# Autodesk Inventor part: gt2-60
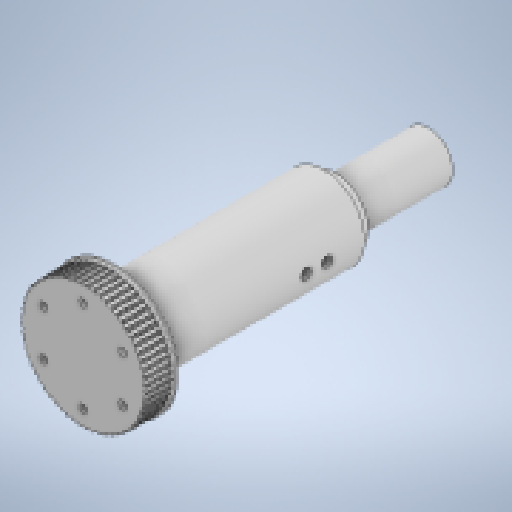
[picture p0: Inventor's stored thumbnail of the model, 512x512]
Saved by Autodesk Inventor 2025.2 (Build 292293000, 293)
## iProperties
Created: 2025-06
Part Number: gt2-60
Material: Generico
Document SubType Name: Modeling
Designer: Ryzen5700u
Density: 1 g/cm^3
Appearance: Default
Author: Ryzen5700u
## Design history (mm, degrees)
sketch "Schizzo1"
  geometry: C1 r 4.963 at (0, 0); A1 r 18.592 centre (0, 0) between (-0.5, -18.585) and (0.5, -18.585); A2 r 0.65 centre (0, -19) between (0.628, -18.833) and (0.5, -18.585); A3 r 0.2 centre (0.822, -18.782) between (0.628, -18.833) and (0.83, -18.982); A4 r 19 centre (0, 0) between (0.83, -18.982) and (1.158, -18.965); A5 r 0.2 centre (1.146, -18.765) between (1.158, -18.965) and (1.344, -18.796); A6 r 0.65 centre (1.986, -18.896) between (1.445, -18.536) and (1.344, -18.796); A7 r 18.592 centre (0, 0) between (1.445, -18.536) and (2.44, -18.431); A8 r 0.65 centre (1.986, -18.896) between (2.593, -18.664) and (2.44, -18.431); A9 r 0.2 centre (2.78, -18.593) between (2.593, -18.664) and (2.81, -18.791); A10 r 19 centre (0, 0) between (2.81, -18.791) and (3.134, -18.74); A11 r 0.2 centre (3.101, -18.542) between (3.134, -18.74) and (3.301, -18.552); A12 r 0.65 centre (3.95, -18.585) between (3.375, -18.283) and (3.301, -18.552); A13 r 18.592 centre (0, 0) between (3.375, -18.283) and (4.354, -18.075); A14 r 0.65 centre (3.95, -18.585) between (4.53, -18.291) and (4.354, -18.075); A15 r 0.2 centre (4.709, -18.201) between (4.53, -18.291) and (4.759, -18.394); A16 r 19 centre (0, 0) between (4.759, -18.394) and (5.076, -18.309); A17 r 0.2 centre (5.023, -18.117) between (5.076, -18.309) and (5.222, -18.106); A18 r 0.65 centre (5.871, -18.07) between (5.267, -17.83) and (5.222, -18.106); A19 r 18.592 centre (0, 0) between (5.267, -17.83) and (6.219, -17.521); A20 r 0.65 centre (5.871, -18.07) between (6.417, -17.717) and (6.219, -17.521); A21 r 0.2 centre (6.585, -17.609) between (6.417, -17.717) and (6.655, -17.796); A22 r 19 centre (0, 0) between (6.655, -17.796) and (6.962, -17.679); A23 r 0.2 centre (6.889, -17.492) between (6.962, -17.679) and (7.086, -17.461); A24 r 0.65 centre (7.728, -17.357) between (7.102, -17.182) and (7.086, -17.461); A25 r 18.592 centre (0, 0) between (7.102, -17.182) and (8.017, -16.775); A26 r 0.65 centre (7.728, -17.357) between (8.234, -16.95) and (8.017, -16.775); A27 r 0.2 centre (8.39, -16.824) between (8.234, -16.95) and (8.479, -17.003); A28 r 19 centre (0, 0) between (8.479, -17.003) and (8.772, -16.854); A29 r 0.2 centre (8.68, -16.677) between (8.772, -16.854) and (8.873, -16.624); A30 r 0.65 centre (9.5, -16.454) between (8.859, -16.346) and (8.873, -16.624); A31 r 18.592 centre (0, 0) between (8.859, -16.346) and (9.726, -15.845); A32 r 0.65 centre (9.5, -16.454) between (9.961, -15.996) and (9.726, -15.845); A33 r 0.2 centre (10.103, -15.855) between (9.961, -15.996) and (10.21, -16.024); A34 r 19 centre (0, 0) between (10.21, -16.024) and (10.486, -15.845); A35 r 0.2 centre (10.375, -15.678) between (10.486, -15.845) and (10.562, -15.606); A36 r 0.65 centre (11.168, -15.371) between (10.519, -15.33) and (10.562, -15.606); A37 r 18.592 centre (0, 0) between (10.519, -15.33) and (11.329, -14.742); A38 r 0.65 centre (11.168, -15.371) between (11.578, -14.867) and (11.329, -14.742); A39 r 0.2 centre (11.704, -14.712) between (11.578, -14.867) and (11.829, -14.869); A40 r 19 centre (0, 0) between (11.829, -14.869) and (12.084, -14.662); A41 r 0.2 centre (11.957, -14.508) between (12.084, -14.662) and (12.135, -14.416); A42 r 0.65 centre (12.713, -14.12) between (12.064, -14.146) and (12.135, -14.416); A43 r 18.592 centre (0, 0) between (12.064, -14.146) and (12.808, -13.477); A44 r 0.65 centre (12.713, -14.12) between (13.069, -13.575) and (12.808, -13.477); A45 r 0.2 centre (13.178, -13.408) between (13.069, -13.575) and (13.318, -13.551); A46 r 19 centre (0, 0) between (13.318, -13.551) and (13.551, -13.318); A47 r 0.2 centre (13.408, -13.178) between (13.551, -13.318) and (13.575, -13.069); A48 r 0.65 centre (14.12, -12.713) between (13.477, -12.808) and (13.575, -13.069); A49 r 18.592 centre (0, 0) between (13.477, -12.808) and (14.146, -12.064); A50 r 0.65 centre (14.12, -12.713) between (14.416, -12.135) and (14.146, -12.064); A51 r 0.2 centre (14.508, -11.957) between (14.416, -12.135) and (14.662, -12.084); A52 r 19 centre (0, 0) between (14.662, -12.084) and (14.869, -11.829); A53 r 0.2 centre (14.712, -11.704) between (14.869, -11.829) and (14.867, -11.578); A54 r 0.65 centre (15.371, -11.168) between (14.742, -11.329) and (14.867, -11.578); A55 r 18.592 centre (0, 0) between (14.742, -11.329) and (15.33, -10.519); A56 r 0.65 centre (15.371, -11.168) between (15.606, -10.562) and (15.33, -10.519); A57 r 0.2 centre (15.678, -10.375) between (15.606, -10.562) and (15.845, -10.486); A58 r 19 centre (0, 0) between (15.845, -10.486) and (16.024, -10.21); A59 r 0.2 centre (15.855, -10.103) between (16.024, -10.21) and (15.996, -9.961); A60 r 0.65 centre (16.454, -9.5) between (15.845, -9.726) and (15.996, -9.961); A61 r 18.592 centre (0, 0) between (15.845, -9.726) and (16.346, -8.859); A62 r 0.65 centre (16.454, -9.5) between (16.624, -8.873) and (16.346, -8.859); A63 r 0.2 centre (16.677, -8.68) between (16.624, -8.873) and (16.854, -8.772); A64 r 19 centre (0, 0) between (16.854, -8.772) and (17.003, -8.479)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; 361 further points
  constraints: 720 point on circle, 361 centre point
extrude "Estrusione1" new body sketch "Schizzo1" stored distance "d0" = 7; taper "d1" = 0 deg
sketch "Schizzo2"
  geometry: C1 r 19.5 at (0, 0); 1 further point
  constraints: 1 centre point, 1 coincident
  dimensions: "d2" = 39 diameter of C1
extrude "Estrusione2" join sketch "Schizzo2" distance "d3" = 1.5; taper "d4" = 0 deg
sketch "Schizzo3"
  geometry: C1 r 12.5 at (0, 0); 1 further point
  constraints: 1 centre point, 1 coincident
  dimensions: "d5" = 25 diameter of C1
extrude "Estrusione3" join sketch "Schizzo3" distance "d6" = 64; taper "d7" = 0 deg
sketch "Schizzo4"
  geometry: C1 r 12.5 at (0, 0) reference; C2 r 10 at (0, 0); C3 r 14 at (0, 0); 1 further point
  constraints: 2 centre point, 1 coincident
  dimensions: "d23" = 1.5 radial gap between concentric circles of C1 C3
extrude "Estrusione4" join sketch "Schizzo4" distance "d9" = 2; taper "d10" = 0 deg
sketch "Schizzo5"
  geometry: 1 further point
hole "Foro1" sketch "Schizzo5" at (0, 0) diameter "d14" = 5.5; stored, may be unused: countersink angle "d18" = 90 deg, drill point angle "d20" = 0 deg; dims "d15" = 6, "d16" = 10, "d17" = 5.7, "d19" = 50
sketch "Schizzo6"
  geometry: L1 (12.1, -66)-(-12.1, -66) reference; C1 r 1.6 at (0, -51); C2 r 1.7 at (0, -52) reference; C3 r 1.6 at (0, -57.5); 1 further point
  constraints: 2 centre point
  dimensions: "d37" = 15 distance from line of L1 C1.centre; "d38" = 3.2 diameter of C1; "d39" = 3.2 diameter of C3; "d40" = 6.5 distance of C3.centre C1.centre
extrude "Estrusione5" cut sketch "Schizzo6" extent not by distance; stored distance "d21" = 0; taper "d22" = 0 deg
fillet "Raccordo1" dims "d24" = 1.5
sketch "Schizzo7"
  geometry: C1 r 12.5 at (0, 0) reference; A1 r 19 centre (0, 0) between (-1.158, -18.965) and (-0.83, -18.982) reference; A2 r 0.2 centre (-0.822, -18.782) between (-0.83, -18.982) and (-0.628, -18.833) reference; A3 r 0.65 centre (0, -19) between (-0.5, -18.585) and (-0.628, -18.833) reference; A4 r 18.592 centre (0, 0) between (-0.5, -18.585) and (0.5, -18.585) reference; A5 r 0.65 centre (0, -19) between (0.628, -18.833) and (0.5, -18.585) reference; A6 r 0.2 centre (0.822, -18.782) between (0.628, -18.833) and (0.83, -18.982) reference; A7 r 19 centre (0, 0) between (0.83, -18.982) and (1.158, -18.965) reference; A8 r 0.2 centre (1.146, -18.765) between (1.158, -18.965) and (1.344, -18.796) reference; A9 r 0.65 centre (1.986, -18.896) between (1.445, -18.536) and (1.344, -18.796) reference; A10 r 18.592 centre (0, 0) between (1.445, -18.536) and (2.44, -18.431) reference; A11 r 0.65 centre (1.986, -18.896) between (2.593, -18.664) and (2.44, -18.431) reference; A12 r 0.2 centre (2.78, -18.593) between (2.593, -18.664) and (2.81, -18.791) reference; A13 r 19 centre (0, 0) between (2.81, -18.791) and (3.134, -18.74) reference; A14 r 0.2 centre (3.101, -18.542) between (3.134, -18.74) and (3.301, -18.552) reference; A15 r 0.65 centre (3.95, -18.585) between (3.375, -18.283) and (3.301, -18.552) reference; A16 r 18.592 centre (0, 0) between (3.375, -18.283) and (4.354, -18.075) reference; A17 r 0.65 centre (3.95, -18.585) between (4.53, -18.291) and (4.354, -18.075) reference; A18 r 0.2 centre (4.709, -18.201) between (4.53, -18.291) and (4.759, -18.394) reference; A19 r 19 centre (0, 0) between (4.759, -18.394) and (5.076, -18.309) reference; A20 r 0.2 centre (5.023, -18.117) between (5.076, -18.309) and (5.222, -18.106) reference; A21 r 0.65 centre (5.871, -18.07) between (5.267, -17.83) and (5.222, -18.106) reference; A22 r 18.592 centre (0, 0) between (5.267, -17.83) and (6.219, -17.521) reference; A23 r 0.65 centre (5.871, -18.07) between (6.417, -17.717) and (6.219, -17.521) reference; A24 r 0.2 centre (6.585, -17.609) between (6.417, -17.717) and (6.655, -17.796) reference; A25 r 19 centre (0, 0) between (6.655, -17.796) and (6.962, -17.679) reference; A26 r 0.2 centre (6.889, -17.492) between (6.962, -17.679) and (7.086, -17.461) reference; A27 r 0.65 centre (7.728, -17.357) between (7.102, -17.182) and (7.086, -17.461) reference; A28 r 18.592 centre (0, 0) between (7.102, -17.182) and (8.017, -16.775) reference; A29 r 0.65 centre (7.728, -17.357) between (8.234, -16.95) and (8.017, -16.775) reference; A30 r 0.2 centre (8.39, -16.824) between (8.234, -16.95) and (8.479, -17.003) reference; A31 r 19 centre (0, 0) between (8.479, -17.003) and (8.772, -16.854) reference; A32 r 0.2 centre (8.68, -16.677) between (8.772, -16.854) and (8.873, -16.624) reference; A33 r 0.65 centre (9.5, -16.454) between (8.859, -16.346) and (8.873, -16.624) reference; A34 r 18.592 centre (0, 0) between (8.859, -16.346) and (9.726, -15.845) reference; A35 r 0.65 centre (9.5, -16.454) between (9.961, -15.996) and (9.726, -15.845) reference; A36 r 0.2 centre (10.103, -15.855) between (9.961, -15.996) and (10.21, -16.024) reference; A37 r 19 centre (0, 0) between (10.21, -16.024) and (10.486, -15.845) reference; A38 r 0.2 centre (10.375, -15.678) between (10.486, -15.845) and (10.562, -15.606) reference; A39 r 0.65 centre (11.168, -15.371) between (10.519, -15.33) and (10.562, -15.606) reference; A40 r 18.592 centre (0, 0) between (10.519, -15.33) and (11.329, -14.742) reference; A41 r 0.65 centre (11.168, -15.371) between (11.578, -14.867) and (11.329, -14.742) reference; A42 r 0.2 centre (11.704, -14.712) between (11.578, -14.867) and (11.829, -14.869) reference; A43 r 19 centre (0, 0) between (11.829, -14.869) and (12.084, -14.662) reference; A44 r 0.2 centre (11.957, -14.508) between (12.084, -14.662) and (12.135, -14.416) reference; A45 r 0.65 centre (12.713, -14.12) between (12.064, -14.146) and (12.135, -14.416) reference; A46 r 18.592 centre (0, 0) between (12.064, -14.146) and (12.808, -13.477) reference; A47 r 0.65 centre (12.713, -14.12) between (13.069, -13.575) and (12.808, -13.477) reference; A48 r 0.2 centre (13.178, -13.408) between (13.069, -13.575) and (13.318, -13.551) reference; A49 r 19 centre (0, 0) between (13.318, -13.551) and (13.551, -13.318) reference; A50 r 0.2 centre (13.408, -13.178) between (13.551, -13.318) and (13.575, -13.069) reference; A51 r 0.65 centre (14.12, -12.713) between (13.477, -12.808) and (13.575, -13.069) reference; A52 r 18.592 centre (0, 0) between (13.477, -12.808) and (14.146, -12.064) reference; A53 r 0.65 centre (14.12, -12.713) between (14.416, -12.135) and (14.146, -12.064) reference; A54 r 0.2 centre (14.508, -11.957) between (14.416, -12.135) and (14.662, -12.084) reference; A55 r 19 centre (0, 0) between (14.662, -12.084) and (14.869, -11.829) reference; A56 r 0.2 centre (14.712, -11.704) between (14.869, -11.829) and (14.867, -11.578) reference; A57 r 0.65 centre (15.371, -11.168) between (14.742, -11.329) and (14.867, -11.578) reference; A58 r 18.592 centre (0, 0) between (14.742, -11.329) and (15.33, -10.519) reference; A59 r 0.65 centre (15.371, -11.168) between (15.606, -10.562) and (15.33, -10.519) reference; A60 r 0.2 centre (15.678, -10.375) between (15.606, -10.562) and (15.845, -10.486) reference; A61 r 19 centre (0, 0) between (15.845, -10.486) and (16.024, -10.21) reference; A62 r 0.2 centre (15.855, -10.103) between (16.024, -10.21) and (15.996, -9.961) reference; A63 r 0.65 centre (16.454, -9.5) between (15.845, -9.726) and (15.996, -9.961) reference; A64 r 18.592 centre (0, 0) between (15.845, -9.726) and (16.346, -8.859) reference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; 1 further point
extrude "Estrusione6" join sketch "Schizzo7" distance "d25" = 1; taper "d26" = 0 deg
sketch "Schizzo8"
  geometry: 4 further points
  constraints: 1 coincident, 1 vertical alignment, 1 other
hole "Foro2" sketch "Schizzo8" at (0, 14) diameter "d27" = 2.4; stored, may be unused: countersink angle "d31" = 90 deg, drill point angle "d33" = 118 deg; dims "d28" = 6, "d29" = 4.4, "d30" = 2.3, "d32" = 7
pattern_circular "Serie circolare1" dims angle "d35" = 360 deg
fillet "Raccordo2" dims "d48" = 0.9
sketch "Schizzo10"
  geometry: C1 r 7.5 at (0, 0); 1 further point
  constraints: 1 centre point, 1 coincident
  dimensions: "d49" = 15 diameter of C1
extrude "Estrusione7" join sketch "Schizzo10" distance "d50" = 32; taper "d51" = 0 deg
sketch "Schizzo11"
  geometry: L1 (-12.5, -69)-(12.5, -69) reference; L2 (12.5, -69)-(9.5, -72.5); L3 (9.5, -72.5)-(7.5, -72.5); L4 (7.5, -69)-(7.5, -101) reference; L5 (0, 0)-(0, -145.566)
  constraints: 6 end point, 1 parallel, 1 point on line, 1 vertical
  dimensions: "d52" = 2 distance of L2.end L3.end; "d53" = 3.5 distance between parallel lines of L1 L3
revolve "Rivoluzione1" sketch "Schizzo11" stored, may be unused: angle "d54" = 90 deg
node "Solido1"
node "Riferimento2"
node "Riferimento3"
node "Linea chiusa proiettata1"
